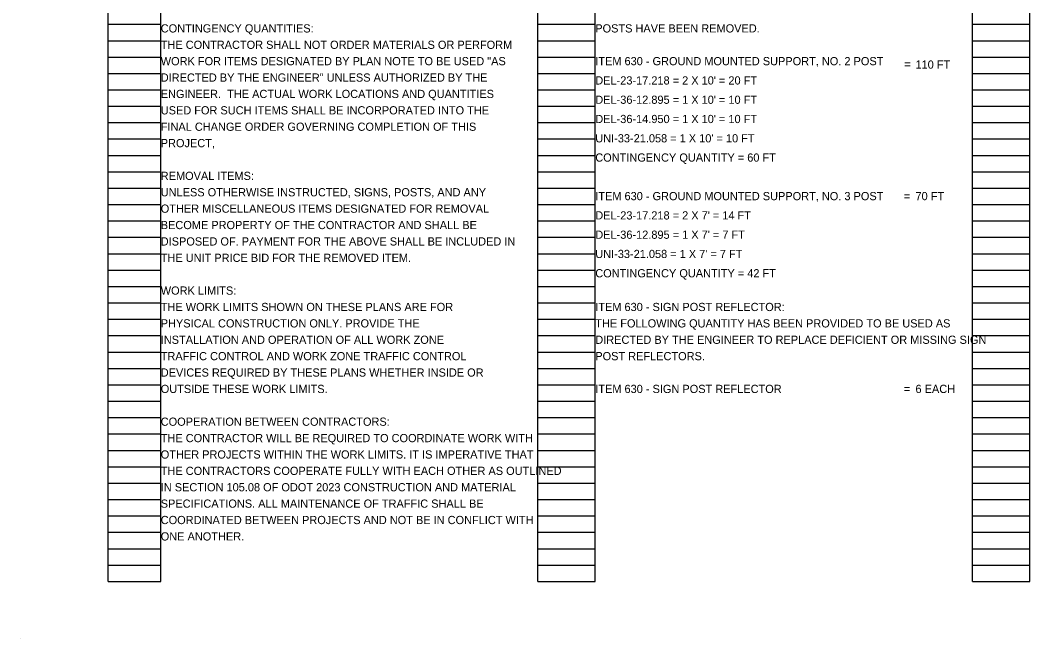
# Model space of a CAD drawing. Extents: x 0 to 32, y 0 to 21.1.
# Drawn here: x 0 to 17.24, y 0 to 10.57 of the extents above; entities that cross this region are included whole.
import ezdxf

# ---------------------------------------------------------------- set-up
doc = ezdxf.new("R2010")
doc.units = 0
doc.layers.add('SH_Data', color=7, linetype='Continuous')
doc.layers.add('SH_Text', color=7, linetype='Continuous')

msp = doc.modelspace()

# ---------------------------------------------------------------- linework, layer by layer
at = {"layer": 'SH_Data'}
for p, q in [((1.5, 0.98), (1.5, 21.14)), ((2.4, 0.98), (2.4, 21.14)), ((8.84, 0.98), (8.84, 21.14)), ((9.82, 0.98), (9.82, 21.14)), ((16.26, 0.98), (16.26, 21.14)), ((17.24, 0.98), (17.24, 21.14)), ((1.5, 10.5), (2.4, 10.5)), ((8.84, 10.5), (9.82, 10.5)), ((16.26, 10.5), (17.24, 10.5)), ((1.5, 10.22), (2.4, 10.22)), ((8.84, 10.22), (9.82, 10.22)), ((16.26, 10.22), (17.24, 10.22)), ((1.5, 9.94), (2.4, 9.94)), ((8.84, 9.94), (9.82, 9.94)), ((16.26, 9.94), (17.24, 9.94)), ((1.5, 9.66), (2.4, 9.66)), ((8.84, 9.66), (9.82, 9.66)), ((16.26, 9.66), (17.24, 9.66)), ((1.5, 9.38), (2.4, 9.38)), ((8.84, 9.38), (9.82, 9.38)), ((16.26, 9.38), (17.24, 9.38)), ((1.5, 9.1), (2.4, 9.1)), ((8.84, 9.1), (9.82, 9.1)), ((16.26, 9.1), (17.24, 9.1)), ((1.5, 8.82), (2.4, 8.82)), ((8.84, 8.82), (9.82, 8.82)), ((16.26, 8.82), (17.24, 8.82)), ((1.5, 8.54), (2.4, 8.54)), ((8.84, 8.54), (9.82, 8.54)), ((16.26, 8.54), (17.24, 8.54)), ((1.5, 8.26), (2.4, 8.26)), ((8.84, 8.26), (9.82, 8.26)), ((16.26, 8.26), (17.24, 8.26)), ((1.5, 7.98), (2.4, 7.98)), ((8.84, 7.98), (9.82, 7.98)), ((16.26, 7.98), (17.24, 7.98)), ((1.5, 7.7), (2.4, 7.7)), ((8.84, 7.7), (9.82, 7.7)), ((16.26, 7.7), (17.24, 7.7)), ((1.5, 7.42), (2.4, 7.42)), ((8.84, 7.42), (9.82, 7.42)), ((16.26, 7.42), (17.24, 7.42)), ((1.5, 7.14), (2.4, 7.14)), ((8.84, 7.14), (9.82, 7.14)), ((16.26, 7.14), (17.24, 7.14)), ((1.5, 6.86), (2.4, 6.86)), ((8.84, 6.86), (9.82, 6.86)), ((16.26, 6.86), (17.24, 6.86)), ((1.5, 6.58), (2.4, 6.58)), ((8.84, 6.58), (9.82, 6.58)), ((16.26, 6.58), (17.24, 6.58)), ((1.5, 6.3), (2.4, 6.3)), ((8.84, 6.3), (9.82, 6.3)), ((16.26, 6.3), (17.24, 6.3)), ((1.5, 6.02), (2.4, 6.02)), ((8.84, 6.02), (9.82, 6.02)), ((16.26, 6.02), (17.24, 6.02)), ((1.5, 5.74), (2.4, 5.74)), ((8.84, 5.74), (9.82, 5.74)), ((16.26, 5.74), (17.24, 5.74)), ((1.5, 5.46), (2.4, 5.46)), ((8.84, 5.46), (9.82, 5.46)), ((16.26, 5.46), (17.24, 5.46)), ((1.5, 5.18), (2.4, 5.18)), ((8.84, 5.18), (9.82, 5.18)), ((16.26, 5.18), (17.24, 5.18)), ((1.5, 4.9), (2.4, 4.9)), ((8.84, 4.9), (9.82, 4.9)), ((16.26, 4.9), (17.24, 4.9)), ((1.5, 4.62), (2.4, 4.62)), ((8.84, 4.62), (9.82, 4.62)), ((16.26, 4.62), (17.24, 4.62)), ((1.5, 4.34), (2.4, 4.34)), ((8.84, 4.34), (9.82, 4.34)), ((16.26, 4.34), (17.24, 4.34)), ((1.5, 4.06), (2.4, 4.06)), ((8.84, 4.06), (9.82, 4.06)), ((16.26, 4.06), (17.24, 4.06)), ((1.5, 3.78), (2.4, 3.78)), ((8.84, 3.78), (9.82, 3.78)), ((16.26, 3.78), (17.24, 3.78)), ((1.5, 3.5), (2.4, 3.5)), ((8.84, 3.5), (9.82, 3.5)), ((16.26, 3.5), (17.24, 3.5)), ((1.5, 3.22), (2.4, 3.22)), ((8.84, 3.22), (9.82, 3.22)), ((16.26, 3.22), (17.24, 3.22)), ((1.5, 2.94), (2.4, 2.94)), ((8.84, 2.94), (9.82, 2.94)), ((16.26, 2.94), (17.24, 2.94)), ((1.5, 2.66), (2.4, 2.66)), ((8.84, 2.66), (9.82, 2.66)), ((16.26, 2.66), (17.24, 2.66)), ((1.5, 2.38), (2.4, 2.38)), ((8.84, 2.38), (9.82, 2.38)), ((16.26, 2.38), (17.24, 2.38)), ((1.5, 2.1), (2.4, 2.1)), ((8.84, 2.1), (9.82, 2.1)), ((16.26, 2.1), (17.24, 2.1)), ((1.5, 1.82), (2.4, 1.82)), ((8.84, 1.82), (9.82, 1.82)), ((16.26, 1.82), (17.24, 1.82)), ((1.5, 1.54), (2.4, 1.54)), ((8.84, 1.54), (9.82, 1.54)), ((16.26, 1.54), (17.24, 1.54)), ((1.5, 1.26), (2.4, 1.26)), ((8.84, 1.26), (9.82, 1.26)), ((16.26, 1.26), (17.24, 1.26)), ((1.5, 0.98), (2.4, 0.98)), ((8.84, 0.98), (9.82, 0.98)), ((16.26, 0.98), (17.24, 0.98)), ((0, 0), (0, 0))]:
    msp.add_line(p, q, dxfattribs=at)

# ---------------------------------------------------------------- texts
for s, p in [('POSTS HAVE BEEN REMOVED.', (9.82, 10.36)), ('ITEM 630 - SIGN POST REFLECTOR:', (9.82, 5.6)), ('THE FOLLOWING QUANTITY HAS BEEN PROVIDED TO BE USED AS ', (9.82, 5.32)), ('DIRECTED BY THE ENGINEER TO REPLACE DEFICIENT OR MISSING SIGN ', (9.82, 5.04)), ('POST REFLECTORS.', (9.82, 4.76)), ('COOPERATION BETWEEN CONTRACTORS:', (2.4, 3.64)), ('THE CONTRACTOR WILL BE REQUIRED TO COORDINATE WORK WITH ', (2.4, 3.36)), ('OTHER PROJECTS WITHIN THE WORK LIMITS. IT IS IMPERATIVE THAT ', (2.4, 3.08)), ('THE CONTRACTORS COOPERATE FULLY WITH EACH OTHER AS OUTLINED ', (2.4, 2.8)), ('IN SECTION 105.08 OF ODOT 2023 CONSTRUCTION AND MATERIAL ', (2.4, 2.52)), ('SPECIFICATIONS. ALL MAINTENANCE OF TRAFFIC SHALL BE ', (2.4, 2.24)), ('COORDINATED BETWEEN PROJECTS AND NOT BE IN CONFLICT WITH ', (2.4, 1.96)), ('ONE ANOTHER.', (2.4, 1.68))]:
    msp.add_text(s, height=0.14, dxfattribs=at).set_placement(p)
at = {"layer": 'SH_Text'}
for s, height, p in [('CONTINGENCY QUANTITIES:', 0.14, (2.4, 10.36)), ('THE CONTRACTOR SHALL NOT ORDER MATERIALS OR PERFORM ', 0.14, (2.4, 10.08)), ('WORK FOR ITEMS DESIGNATED BY PLAN NOTE TO BE USED "AS ', 0.14, (2.4, 9.8)), ('ITEM 630 - GROUND MOUNTED SUPPORT, NO. 2 POST', 0.14, (9.82, 9.8)), ('=', 0.154, (15.091, 9.742)), ('110 FT', 0.14, (15.288, 9.742)), ('DIRECTED BY THE ENGINEER" UNLESS AUTHORIZED BY THE ', 0.14, (2.4, 9.52)), ("DEL-23-17.218 = 2 X 10' = 20 FT", 0.14, (9.82, 9.471)), ('ENGINEER.  THE ACTUAL WORK LOCATIONS AND QUANTITIES ', 0.14, (2.4, 9.24)), ("DEL-36-12.895 = 1 X 10' = 10 FT", 0.14, (9.82, 9.141)), ('USED FOR SUCH ITEMS SHALL BE INCORPORATED INTO THE ', 0.14, (2.4, 8.96)), ('FINAL CHANGE ORDER GOVERNING COMPLETION OF THIS ', 0.14, (2.4, 8.68)), ("DEL-36-14.950 = 1 X 10' = 10 FT", 0.14, (9.82, 8.812)), ("UNI-33-21.058 = 1 X 10' = 10 FT", 0.14, (9.82, 8.482)), ('PROJECT,', 0.14, (2.4, 8.4)), ('CONTINGENCY QUANTITY = 60 FT', 0.14, (9.82, 8.153)), ('REMOVAL ITEMS:', 0.14, (2.4, 7.84)), ('UNLESS OTHERWISE INSTRUCTED, SIGNS, POSTS, AND ANY ', 0.14, (2.4, 7.56)), ('ITEM 630 - GROUND MOUNTED SUPPORT, NO. 3 POST', 0.14, (9.82, 7.494)), ('=', 0.14, (15.091, 7.494)), ('70 FT', 0.14, (15.288, 7.494)), ('OTHER MISCELLANEOUS ITEMS DESIGNATED FOR REMOVAL ', 0.14, (2.4, 7.28)), ("DEL-23-17.218 = 2 X 7' = 14 FT", 0.14, (9.82, 7.165)), ('BECOME PROPERTY OF THE CONTRACTOR AND SHALL BE ', 0.14, (2.4, 7)), ("DEL-36-12.895 = 1 X 7' = 7 FT", 0.14, (9.82, 6.835)), ('DISPOSED OF. PAYMENT FOR THE ABOVE SHALL BE INCLUDED IN ', 0.14, (2.4, 6.72)), ('THE UNIT PRICE BID FOR THE REMOVED ITEM.', 0.14, (2.4, 6.44)), ("UNI-33-21.058 = 1 X 7' = 7 FT", 0.14, (9.82, 6.506)), ('CONTINGENCY QUANTITY = 42 FT', 0.14, (9.82, 6.176)), ('WORK LIMITS:', 0.14, (2.4, 5.88)), ('THE WORK LIMITS SHOWN ON THESE PLANS ARE FOR', 0.14, (2.4, 5.6)), ('PHYSICAL CONSTRUCTION ONLY. PROVIDE THE', 0.14, (2.4, 5.32)), ('INSTALLATION AND OPERATION OF ALL WORK ZONE', 0.14, (2.4, 5.04)), ('TRAFFIC CONTROL AND WORK ZONE TRAFFIC CONTROL', 0.14, (2.4, 4.76)), ('DEVICES REQUIRED BY THESE PLANS WHETHER INSIDE OR', 0.14, (2.4, 4.48)), ('OUTSIDE THESE WORK LIMITS.', 0.14, (2.4, 4.2)), ('ITEM 630 - SIGN POST REFLECTOR', 0.14, (9.82, 4.2)), ('6 EACH', 0.14, (15.288, 4.2)), ('=', 0.14, (15.091, 4.2))]:
    msp.add_text(s, height=height, dxfattribs=at).set_placement(p)

doc.saveas('drawing.dxf')
